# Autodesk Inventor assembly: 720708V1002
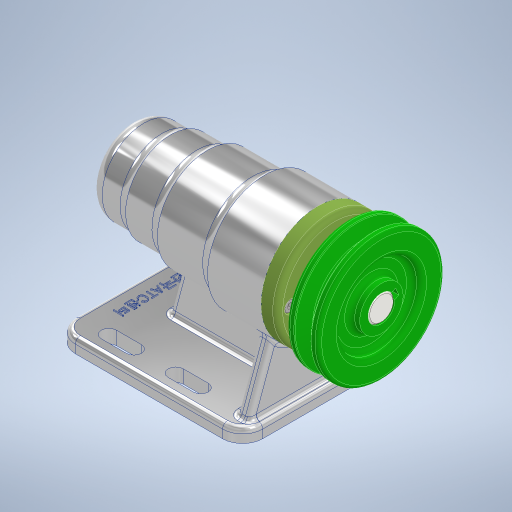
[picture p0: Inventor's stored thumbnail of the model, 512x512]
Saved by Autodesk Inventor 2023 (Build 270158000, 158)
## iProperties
Created: 2022-07
Part Number: 720708V1002
Document SubType Name: Assembly
Designer: owner
Author: owner
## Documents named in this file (12)
- C:\Users\owner\Desktop\720708V1002\720708V1002.iam
- C:\Users\owner\Desktop\720708V1002\본체.ipt
- C:\Users\owner\Desktop\720708V1002\V벨트풀리.ipt
- C:\Users\owner\Desktop\720708V1002\멈춤나사 M3.ipt
- C:\Users\owner\Desktop\720708V1002\베어링 6004.ipt
- C:\Users\owner\Desktop\720708V1002\베어링 51202.ipt
- C:\Users\owner\Desktop\720708V1002\볼트 M4.ipt
- C:\Users\owner\Desktop\720708V1002\어댑터슬리브.ipt
- C:\Users\owner\Desktop\720708V1002\오일 실 20x35x7.ipt
- C:\Users\owner\Desktop\720708V1002\축.ipt
- C:\Users\owner\Desktop\720708V1002\커버.ipt
- C:\Users\owner\Desktop\720708V1002\키 5x5.ipt
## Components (1 placed, 1 different names)
1. V벨트풀리:1
